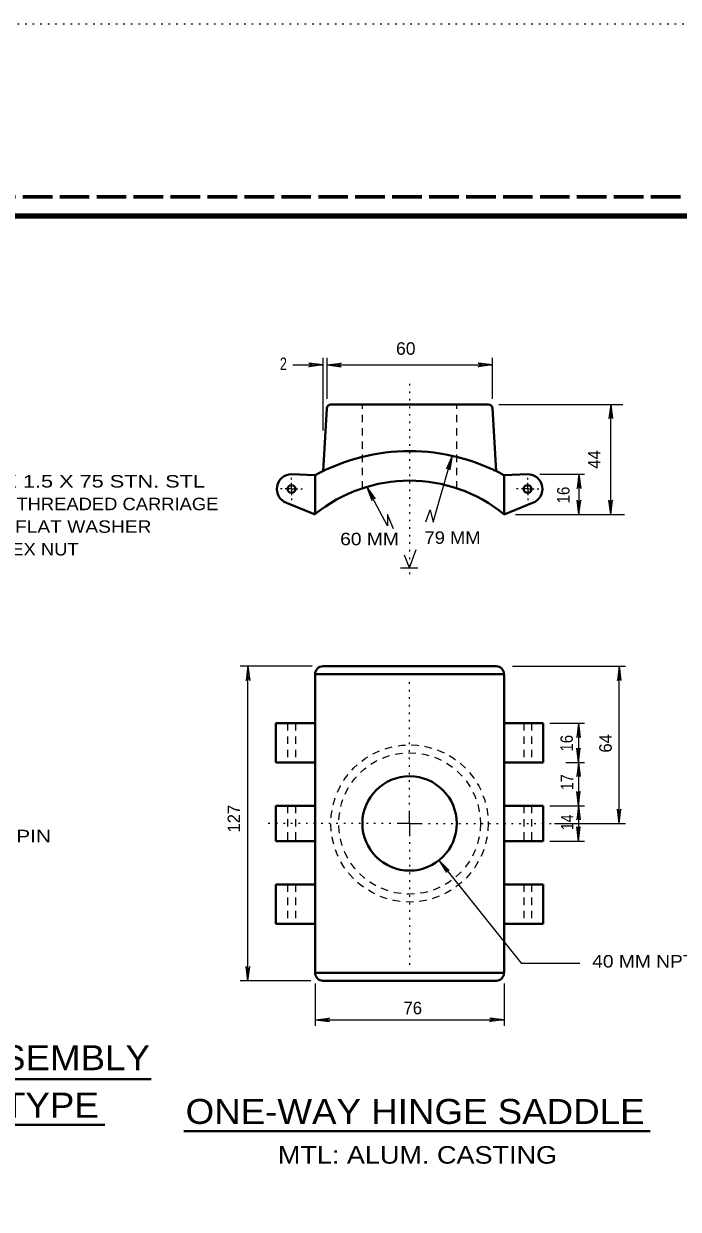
# Model space of a CAD drawing. Extents: x 312583 to 312854, y 144419 to 144597.
# Drawn here: x 312685.8 to 312725.6, y 144524.5 to 144596.8 of the extents above; entities that cross this region are included whole.
import ezdxf
from ezdxf.enums import TextEntityAlignment as Align

# ---------------------------------------------------------------- set-up
doc = ezdxf.new("R2010")
doc.units = 0
doc.header["$LTSCALE"] = 0.3
for name, pattern in [('DOTTED', [1.5, 0.3, -1.2]), ('LONG_DASHED', [7.5, 6, -1.5]), ('SHORT_DASHED', [2.7, 1.5, -1.2])]:
    doc.linetypes.add(name, pattern=pattern)
for name, color, linetype, lineweight in [('1', 7, 'Continuous', 40), ('2', 7, 'Continuous', 13), ('62', 7, 'DOTTED', 13), ('63', 7, 'LONG_DASHED', 60)]:
    doc.layers.add(name, color=color, linetype=linetype, lineweight=lineweight)

msp = doc.modelspace()

# ---------------------------------------------------------------- linework, layer by layer
at = {"layer": '1', "linetype": 'DOTTED', "lineweight": 13}
msp.add_line((312709.259, 144574.8373), (312709.259, 144563.1073), dxfattribs=at)
at = {"layer": '1'}
for p, q in [((312704.2143, 144573.3423), (312703.9843, 144569.5166)), ((312704.4673, 144573.58), (312714.066, 144573.58)), ((312714.3037, 144573.35), (312714.526, 144569.5166)), ((312703.509, 144569.2636), (312702.0677, 144569.3326)), ((312703.509, 144566.8716), (312703.509, 144569.2636)), ((312703.509, 144566.8716), (312701.761, 144567.5846)), ((312715.009, 144566.8716), (312716.7493, 144567.5846)), ((312703.9843, 144557.6256), (312714.526, 144557.6256)), ((312703.509, 144557.1503), (312703.509, 144538.942)), ((312703.509, 144557.1503), (312715.009, 144557.1503)), ((312715.009, 144557.1503), (312715.009, 144538.942)), ((312701.1093, 144554.1526), (312701.1093, 144551.7606)), ((312703.509, 144554.1526), (312701.1093, 144554.1526)), ((312715.009, 144554.1526), (312717.401, 144554.1526)), ((312717.401, 144554.1526), (312717.401, 144551.7606)), ((312703.509, 144551.7606), (312701.1093, 144551.7606)), ((312715.009, 144551.7606), (312717.401, 144551.7606)), ((312703.509, 144549.1233), (312701.1093, 144549.1233)), ((312701.1093, 144549.1233), (312701.1093, 144546.969)), ((312715.009, 144549.1233), (312717.401, 144549.1233)), ((312717.401, 144549.1233), (312717.401, 144546.969)), ((312703.509, 144546.969), (312701.1093, 144546.969)), ((312715.009, 144546.969), (312717.401, 144546.969)), ((312703.509, 144544.3316), (312701.1093, 144544.3316)), ((312701.1093, 144541.932), (312701.1093, 144544.3316)), ((312715.009, 144544.3316), (312717.401, 144544.3316)), ((312717.401, 144541.932), (312717.401, 144544.3316)), ((312703.509, 144541.932), (312701.1093, 144541.932)), ((312715.009, 144541.932), (312717.401, 144541.932)), ((312703.509, 144538.942), (312715.009, 144538.942)), ((312703.9843, 144538.459), (312714.526, 144538.459))]:
    msp.add_line(p, q, dxfattribs=at)
at = {"layer": '1', "linetype": 'SHORT_DASHED', "lineweight": 25}
for p, q in [((312706.384, 144568.451), (312706.384, 144573.58)), ((312712.134, 144568.451), (312712.134, 144573.58)), ((312701.83, 144554.1526), (312701.83, 144551.7606)), ((312702.3053, 144554.1526), (312702.3053, 144551.7606)), ((312716.205, 144554.1526), (312716.205, 144551.7606)), ((312716.688, 144554.1526), (312716.688, 144551.7606)), ((312701.83, 144549.1233), (312701.83, 144546.969)), ((312702.3053, 144549.1233), (312702.3053, 144546.969)), ((312716.205, 144549.1233), (312716.205, 144546.969)), ((312716.688, 144549.1233), (312716.688, 144546.969)), ((312701.83, 144544.3316), (312701.83, 144541.932)), ((312702.3053, 144544.3316), (312702.3053, 144541.932)), ((312716.205, 144544.3316), (312716.205, 144541.932)), ((312716.688, 144544.3316), (312716.688, 144541.932))]:
    msp.add_line(p, q, dxfattribs=at)
at = {"layer": '1', "lineweight": 158}
msp.add_lwpolyline([(312616.5, 144423.1446), (312616.5, 144585.0846), (312849, 144585.0846)], dxfattribs=at)
at = {"layer": '1'}
msp.add_lwpolyline([(312715.009, 144566.8716), (312715.009, 144569.2636), (312716.4427, 144569.3326)], dxfattribs=at)
for centre, radius in [((312702.0658, 144568.428), 0.2396), ((312716.4446, 144568.428), 0.2396), ((312709.2552, 144548.0423), 2.875)]:
    msp.add_circle(centre, radius, dxfattribs=at)
at = {"layer": '1', "linetype": 'SHORT_DASHED', "lineweight": 25}
for radius in [4.7917, 4.3125]:
    msp.add_circle((312709.2552, 144548.0423), radius, dxfattribs=at)
at = {"layer": '1'}
for centre, radius, start, end in [((312704.4654, 144573.3366), 0.2396, 90, 180), ((312714.0624, 144573.3366), 0.2396, 3.34745, 90), ((312709.2552, 144558.7565), 11.9792, 61.31051, 118.68949), ((312709.2552, 144558.7565), 11.9792, 61.31051, 118.68949), ((312702.0692, 144568.428), 0.9008, 90, 250.00754), ((312709.2552, 144559.8336), 9.1042, 50.73611, 129.25886), ((312716.4412, 144568.428), 0.9008, 289.99246, 90), ((312703.9843, 144557.1465), 0.4792, 90, 180), ((312714.526, 144557.1465), 0.4792, 0, 90), ((312703.9843, 144538.9381), 0.4792, 180, 270), ((312714.526, 144538.9381), 0.4792, 270, 0)]:
    msp.add_arc(centre, radius, start, end, dxfattribs=at)
at = {"layer": '2'}
for p, q in [((312703.118, 144576.0946), (312703.394, 144575.9873)), ((312703.9843, 144575.9873), (312703.118, 144576.0946)), ((312703.9843, 144571.9853), (312703.9843, 144576.4243)), ((312704.2297, 144573.9173), (312704.2297, 144576.4243)), ((312704.2297, 144575.9873), (312705.096, 144576.0946)), ((312705.096, 144576.0946), (312704.82, 144575.9873)), ((312713.4373, 144576.0946), (312713.7133, 144575.9873)), ((312714.3037, 144575.9873), (312713.4373, 144576.0946)), ((312714.3037, 144573.9173), (312714.3037, 144576.4243)), ((312702.152, 144575.9873), (312703.9843, 144575.9873)), ((312703.118, 144575.88), (312703.394, 144575.9873)), ((312703.9843, 144575.9873), (312703.118, 144575.88)), ((312704.2297, 144575.9873), (312714.3037, 144575.9873)), ((312704.2297, 144575.9873), (312705.096, 144575.88)), ((312705.096, 144575.88), (312704.82, 144575.9873)), ((312713.4373, 144575.88), (312713.7133, 144575.9873)), ((312714.3037, 144575.9873), (312713.4373, 144575.88)), ((312714.687, 144573.58), (312722.2463, 144573.58)), ((312721.5027, 144573.58), (312721.3953, 144572.7136)), ((312721.5027, 144566.8716), (312721.5027, 144573.58)), ((312721.5027, 144573.58), (312721.61, 144572.7136)), ((312721.3953, 144572.7136), (312721.5027, 144572.9896)), ((312721.61, 144572.7136), (312721.5027, 144572.9896)), ((312711.8427, 144570.452), (312711.5053, 144569.647)), ((312711.8427, 144570.452), (312711.7123, 144569.5933)), ((312711.5053, 144569.647), (312711.6817, 144569.8846)), ((312711.7123, 144569.5933), (312711.6817, 144569.8846)), ((312702.0677, 144568.428), (312702.0677, 144568.8113)), ((312716.4503, 144568.428), (312716.4503, 144568.8113)), ((312717.194, 144569.3326), (312719.9157, 144569.3326)), ((312719.5707, 144569.3326), (312719.4633, 144568.4663)), ((312719.5707, 144569.3326), (312719.5707, 144566.8716)), ((312719.5707, 144569.3326), (312719.678, 144568.4663)), ((312702.0677, 144568.428), (312701.6843, 144568.428)), ((312702.0677, 144568.428), (312702.451, 144568.428)), ((312702.0677, 144568.428), (312702.0677, 144568.0446)), ((312706.6523, 144568.5353), (312706.9667, 144567.7226)), ((312706.6523, 144568.5353), (312707.1583, 144567.8223)), ((312716.4503, 144568.428), (312716.067, 144568.428)), ((312716.4503, 144568.428), (312716.8337, 144568.428)), ((312716.4503, 144568.428), (312716.4503, 144568.0446)), ((312719.4633, 144568.4663), (312719.5707, 144568.7423)), ((312719.678, 144568.4663), (312719.5707, 144568.7423)), ((312706.9667, 144567.7226), (312706.9283, 144568.014)), ((312707.1583, 144567.8223), (312706.9283, 144568.014)), ((312719.4633, 144567.738), (312719.5707, 144567.462)), ((312719.5707, 144566.8716), (312719.4633, 144567.738)), ((312719.678, 144567.738), (312719.5707, 144567.462)), ((312719.5707, 144566.8716), (312719.678, 144567.738)), ((312721.3953, 144567.738), (312721.5027, 144567.462)), ((312721.5027, 144566.8716), (312721.3953, 144567.738)), ((312721.61, 144567.738), (312721.5027, 144567.462)), ((312721.5027, 144566.8716), (312721.61, 144567.738)), ((312708.27, 144566.0053), (312707.9097, 144566.8793)), ((312710.248, 144566.427), (312710.5087, 144567.1476)), ((312715.699, 144566.8716), (312722.346, 144566.8716)), ((312709.259, 144563.6286), (312709.6577, 144564.748)), ((312709.259, 144563.6286), (312708.937, 144564.403)), ((312708.707, 144563.6286), (312709.7573, 144563.6286)), ((312703.3327, 144557.6256), (312698.932, 144557.6256)), ((312699.415, 144557.6256), (312699.3077, 144556.7593)), ((312699.415, 144538.459), (312699.415, 144557.6256)), ((312699.415, 144557.6256), (312699.5223, 144556.7593)), ((312715.515, 144557.6256), (312722.415, 144557.6256)), ((312722.024, 144557.6256), (312721.9167, 144556.7593)), ((312722.024, 144548.0423), (312722.024, 144557.6256)), ((312722.024, 144557.6256), (312722.1313, 144556.7593)), ((312699.3077, 144556.7593), (312699.415, 144557.0353)), ((312699.5223, 144556.7593), (312699.415, 144557.0353)), ((312721.9167, 144556.7593), (312722.024, 144557.0353)), ((312722.1313, 144556.7593), (312722.024, 144557.0353)), ((312717.7997, 144554.1526), (312719.908, 144554.1526)), ((312719.5477, 144554.1526), (312719.4403, 144553.2863)), ((312719.5477, 144554.1526), (312719.5477, 144551.7606)), ((312719.5477, 144554.1526), (312719.655, 144553.2863)), ((312719.4403, 144553.2863), (312719.5477, 144553.5623)), ((312719.655, 144553.2863), (312719.5477, 144553.5623)), ((312719.4403, 144552.627), (312719.5477, 144552.351)), ((312719.5477, 144551.7606), (312719.4403, 144552.627)), ((312719.655, 144552.627), (312719.5477, 144552.351)), ((312719.5477, 144551.7606), (312719.655, 144552.627)), ((312718.781, 144551.7606), (312719.908, 144551.7606)), ((312719.5477, 144551.7606), (312719.4403, 144550.8942)), ((312719.5477, 144551.7606), (312719.655, 144550.8942)), ((312719.4403, 144550.8942), (312719.5477, 144551.1702)), ((312719.655, 144550.8942), (312719.5477, 144551.1702)), ((312719.4403, 144549.9896), (312719.5477, 144549.7136)), ((312719.5477, 144549.1233), (312719.4403, 144549.9896)), ((312719.655, 144549.9896), (312719.5477, 144549.7136)), ((312719.5477, 144549.1233), (312719.655, 144549.9896)), ((312709.259, 144548.0423), (312709.259, 144548.809)), ((312717.7997, 144549.1233), (312719.908, 144549.1233)), ((312719.5477, 144549.1233), (312719.4403, 144548.2569)), ((312719.5477, 144549.1233), (312719.655, 144548.2569)), ((312721.9167, 144548.9086), (312722.024, 144548.6326)), ((312722.024, 144548.0423), (312721.9167, 144548.9086)), ((312722.1313, 144548.9086), (312722.024, 144548.6326)), ((312722.024, 144548.0423), (312722.1313, 144548.9086)), ((312709.259, 144548.0423), (312708.4923, 144548.0423)), ((312709.259, 144548.0423), (312710.0257, 144548.0423)), ((312709.259, 144548.0423), (312709.259, 144547.2756)), ((312718.0757, 144548.0423), (312722.415, 144548.0423)), ((312719.4403, 144548.2569), (312719.5477, 144548.5329)), ((312719.655, 144548.2569), (312719.5477, 144548.5329)), ((312719.4403, 144547.8353), (312719.5477, 144547.5593)), ((312719.5477, 144546.969), (312719.4403, 144547.8353)), ((312719.655, 144547.8353), (312719.5477, 144547.5593)), ((312719.5477, 144546.969), (312719.655, 144547.8353)), ((312717.7997, 144546.969), (312719.908, 144546.969)), ((312711.0453, 144545.796), (312711.5053, 144545.0523)), ((312711.0453, 144545.796), (312711.674, 144545.1826)), ((312711.5053, 144545.0523), (312711.4133, 144545.336)), ((312711.674, 144545.1826), (312711.4133, 144545.336)), ((312699.3077, 144539.3253), (312699.415, 144539.0493)), ((312699.415, 144538.459), (312699.3077, 144539.3253)), ((312699.5223, 144539.3253), (312699.415, 144539.0493)), ((312699.415, 144538.459), (312699.5223, 144539.3253)), ((312703.2407, 144538.459), (312698.932, 144538.459)), ((312703.509, 144538.298), (312703.509, 144535.699)), ((312715.009, 144538.298), (312715.009, 144535.699)), ((312703.509, 144536.0746), (312704.3753, 144536.182)), ((312703.509, 144536.0746), (312715.009, 144536.0746)), ((312703.509, 144536.0746), (312704.3753, 144535.9673)), ((312704.3753, 144536.182), (312704.0993, 144536.0746)), ((312704.3753, 144535.9673), (312704.0993, 144536.0746)), ((312714.1427, 144536.182), (312714.4187, 144536.0746)), ((312715.009, 144536.0746), (312714.1427, 144536.182)), ((312714.1427, 144535.9673), (312714.4187, 144536.0746)), ((312715.009, 144536.0746), (312714.1427, 144535.9673))]:
    msp.add_line(p, q, dxfattribs=at)
at = {"layer": '2', "linetype": 'DOTTED'}
for p, q in [((312702.0677, 144569.003), (312702.0677, 144569.2253)), ((312716.4503, 144569.003), (312716.4503, 144569.2636)), ((312701.4927, 144568.428), (312701.347, 144568.428)), ((312702.6427, 144568.428), (312702.934, 144568.428)), ((312715.8753, 144568.428), (312715.515, 144568.428)), ((312717.0253, 144568.428), (312717.2093, 144568.428)), ((312702.0677, 144567.853), (312702.0677, 144567.7533)), ((312716.4503, 144567.853), (312716.4503, 144567.7226)), ((312709.259, 144549.1923), (312709.259, 144556.859)), ((312708.109, 144548.0423), (312700.4423, 144548.0423)), ((312710.409, 144548.0423), (312718.0757, 144548.0423)), ((312709.259, 144546.8923), (312709.259, 144539.2256))]:
    msp.add_line(p, q, dxfattribs=at)
at = {"layer": '2', "lineweight": 40}
for p, q in [((312666.2407, 144532.4572), (312693.5247, 144532.4572)), ((312668.2958, 144529.6657), (312690.69, 144529.6657)), ((312695.4982, 144529.282), (312723.9161, 144529.282))]:
    msp.add_line(p, q, dxfattribs=at)
at = {"layer": '2'}
for points in [[(312710.5087, 144567.1476), (312710.685, 144566.3963), (312711.8427, 144570.452)], [(312707.9097, 144566.8793), (312707.9097, 144566.1816), (312706.6523, 144568.5353)], [(312719.5477, 144551.7606), (312719.5477, 144549.1233), (312719.5477, 144546.969)], [(312711.0453, 144545.796), (312716.044, 144539.5246), (312719.6278, 144539.5246)]]:
    msp.add_lwpolyline(points, dxfattribs=at)
at = {"layer": '62'}
msp.add_line((312601.2, 144596.7846), (312853.5, 144596.7846), dxfattribs=at)
at = {"layer": '63'}
msp.add_line((312851.75, 144586.2246), (312583.526, 144586.2246), dxfattribs=at)

# ---------------------------------------------------------------- texts
at = {"layer": '2'}
for s, width, p in [('60', 1.05, (312708.4316, 144576.6093)), ('2', 0.75, (312701.3586, 144575.6778)), ('M10 X 1.5 X 75 STN. STL', 1.3, (312681.5226, 144568.5156)), ('FULLY THREADED CARRIAGE', 1.1, (312681.5226, 144567.1356)), ('BOLT, FLAT WASHER', 1.15, (312681.5226, 144565.7556)), ('60 MM', 1.15, (312705.0288, 144565.001)), ('79 MM', 1.1, (312710.165, 144565.0825)), ('AND HEX NUT', 1.1, (312681.5226, 144564.3756)), ('75 MM LG. PIN', 1.25, (312678.6651, 144546.8956)), ('40 MM NPT THREAD', 1.15, (312720.3775, 144539.263))]:
    msp.add_text(s, height=0.76, dxfattribs=dict(at, width=width)).set_placement(p)
for s, p in [('44', (312720.8806, 144569.6566)), ('64', (312721.5679, 144552.3591)), ('127', (312698.9355, 144547.4846))]:
    msp.add_text(s, height=0.76, rotation=90, dxfattribs=at).set_placement(p)
for s, width, p in [('16', 0.9, (312718.997, 144567.5487)), ('16', 0.9, (312719.2012, 144552.4214)), ('17', 0.85, (312719.2237, 144550.0715)), ('14', 0.85, (312719.231, 144547.6297))]:
    msp.add_text(s, height=0.76, rotation=90, dxfattribs=dict(at, width=width)).set_placement(p)
msp.add_text('76', height=0.76, dxfattribs=at).set_placement((312708.8847, 144536.4129))
for s, height, width, p in [('POLE CLAMP ASSEMBLY', 1.52, 1.1, (312679.9627, 144533.0028)), ('HINGE STRAP TYPE', 1.52, 1.1, (312679.5221, 144530.1124)), ('ONE-WAY HINGE SADDLE', 1.52, 1.1, (312709.5922, 144529.7287)), ('MTL: ALUM. CASTING', 1.07, 1.15, (312709.7366, 144527.3074))]:
    msp.add_text(s, height=height, dxfattribs=dict(at, width=width)).set_placement(p, align=Align.CENTER)

doc.saveas('drawing.dxf')
